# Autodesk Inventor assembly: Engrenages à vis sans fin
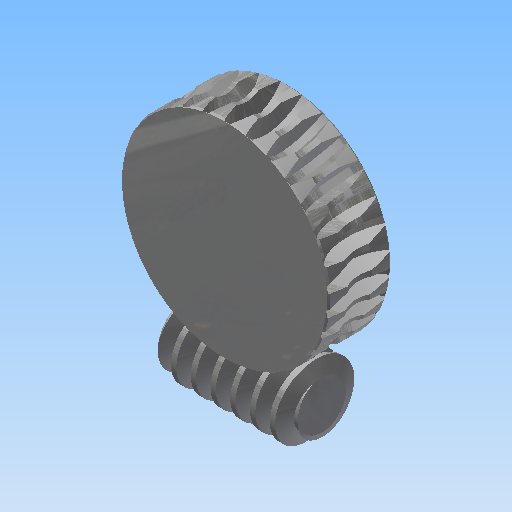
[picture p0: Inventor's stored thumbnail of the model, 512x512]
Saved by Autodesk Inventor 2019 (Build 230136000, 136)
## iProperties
Created: 2023-04
Part Number: Engrenages à vis sans fin
Document SubType Name: Assembly
Designer: Thier
Categories: <?xml version="1.0" encoding="UTF-16"?> <MemberInstance><Categories><FamilyTemplate/><ParamToTemplateMap><ParamToTemplate><ParamToTemplate CategoryParameter="//
ClientObjectVersion: 1
Author: Thier
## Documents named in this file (3)
- C:\Travail\PREPA\EC02\TP\TP3-Arbre\EC02-T03-Pieces-SEMoteur\SERoueVis\Design Accelerator\Engrenages à vis sans fin1.iam
- C:\Travail\PREPA\EC02\TP\TP3-Arbre\EC02-T03-Pieces-SEMoteur\SERoueVis\Design Accelerator\Vis sans fin1.ipt
- C:\Travail\PREPA\EC02\TP\TP3-Arbre\EC02-T03-Pieces-SEMoteur\SERoueVis\Design Accelerator\Engrenage à vis sans fin1.ipt
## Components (2 placed, 2 different names)
1. Vis sans fin:1 — Rotation:1
2. Engrenage à vis sans fin:1 — Rotation:1
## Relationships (1: RelateRotation 1)
- Rotation:1 [RelateRotation]: Vis sans fin:1 ↔ Engrenage à vis sans fin:1
